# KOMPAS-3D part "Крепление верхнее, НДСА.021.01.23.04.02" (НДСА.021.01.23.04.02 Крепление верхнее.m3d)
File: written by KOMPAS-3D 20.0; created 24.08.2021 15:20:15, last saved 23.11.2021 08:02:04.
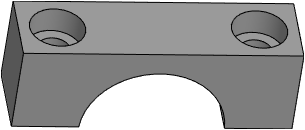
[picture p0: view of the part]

Document properties: Полное имя файла: C:\Users\s.pischagina\Desktop\PLM\НДСА.021.01.23.04.02 Крепление верхнее.m3d

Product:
- Part/product: Крепление верхнее  | designation НДСА.021.01.23.04.02
    Материал: АМг6  ГОСТ 4784-2019 (density 2640 kg/m3)
    Масса: 0.0182029
    additional columns: <item xmlns="http://appius.ru/pdm" xmlns:xs="http://www.w3.org/2001/XMLSchema" x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; <item xmlns="http://appius.ru/pdm" xmlns:xs="http://www.w3.org/2001/XMLSchema" x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; <item xmlns="http://appius.ru/pdm" xmlns:xs="http://www.w3.org/2001/XMLSchema" x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
    source file: НДСА.002.01.05.02.00 Крепление верхнее.cdw, НДСА.021.01.23.04.02 Крепление верхнее.cdw

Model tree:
1. Эскиз:1
2. Элемент выдавливания:1
     Расстояние 1 = 70
3. Эскиз:2  (with: Элемент выдавливания:1)
4. Элемент выдавливания:2
     Расстояние 2 = 107
5. Эскиз:3  (with: Элемент выдавливания:1, Элемент выдавливания:2)
6. Элемент выдавливания:3
     Расстояние 2 = 14
7. Отверстие:1  (with: Элемент выдавливания:1)
     Глубина выреза = 70; Диаметр отверстия = 6; Угол конуса дна = 118; Расстояние 1 = 7; Расстояние 2 = 13; Диаметр цековки = 10; Глубина цековки = 5
8. M5  (with: Элемент выдавливания:3)  (labels: M5; cil0_24705-2004 coarse)
     Длина резьбы = 30; Шаг резьбы = 0.8; Номинальный диаметр резьбы = 5
9. Отверстие:2  (with: Элемент выдавливания:1, M5, Элемент выдавливания:3)  (labels: M5; cil0_24705-2004 coarse)
     Глубина выреза = 70; Диаметр отверстия = 6; Угол конуса дна = 118; Расстояние 1 = 7; Расстояние 2 = 49; Диаметр цековки = 10; Глубина цековки = 5; Длина резьбы = 30; Шаг резьбы = 0.8; Номинальный диаметр резьбы = 5
10. Эскиз:4  (with: Элемент выдавливания:3)
11. Элемент выдавливания:4
12. Эскиз:5  (with: Элемент выдавливания:1)
13. Элемент выдавливания:5  (with: Элемент выдавливания:1)
     Расстояние 2 = 6
14. Элемент выдавливания:6  (with: Элемент выдавливания:1)  (labels: АМг6  ГОСТ 4784-2019)
     Расстояние 2 = 6

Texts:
  НДСА.021.01.23.04.02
